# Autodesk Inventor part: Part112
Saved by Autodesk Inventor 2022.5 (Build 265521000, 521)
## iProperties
Created: 2024-12
Part Number: Part112
Material: Generic
Document SubType Name: Modeling
Designer: AdminForWorker
Density: 1 g/cm^3
Appearance: Default
Author: AdminForWorker
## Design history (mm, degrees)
feature "Body1"
body "Solid1"
